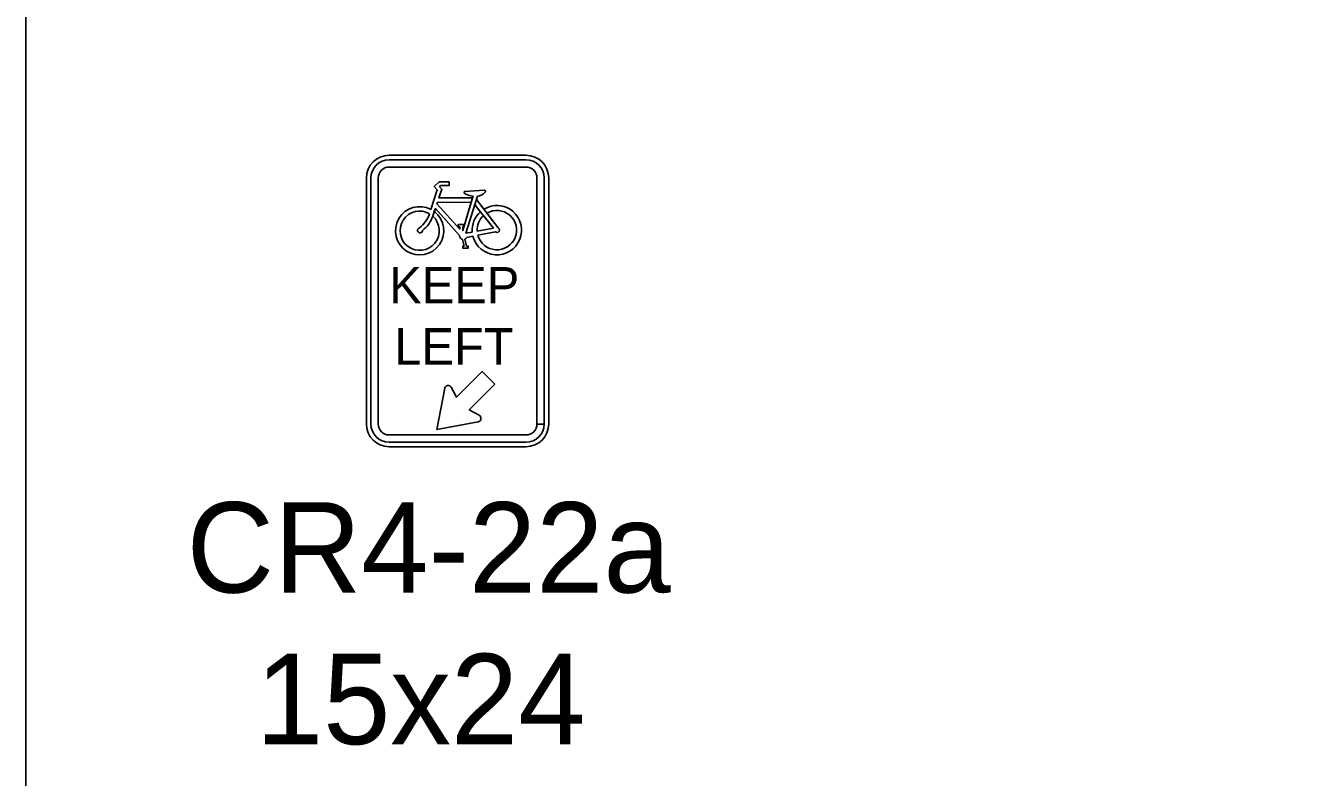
# Model space of a CAD drawing. Extents: x 1458 to 4498, y 17709 to 24109.
# Drawn here: x 1458.4 to 1670.2, y 20684 to 20807.7 of the extents above; entities that cross this region are included whole.
import ezdxf

# ---------------------------------------------------------------- set-up
doc = ezdxf.new("R2010")
doc.units = 0
doc.layers.add('P_TRAF_TCP_General', color=7, linetype='Continuous')

msp = doc.modelspace()

# ---------------------------------------------------------------- linework, layer by layer
at = {"layer": 'P_TRAF_TCP_General'}
for p, q in [((1518.22, 20786.39), (1540.72, 20786.39)), ((1518.22, 20785.64), (1540.72, 20785.64)), ((1540.72, 20784.44), (1518.22, 20784.44)), ((1514.47, 20742.14), (1514.47, 20782.64)), ((1515.22, 20742.14), (1515.22, 20782.64)), ((1516.42, 20782.64), (1516.42, 20742.14)), ((1542.52, 20742.14), (1542.52, 20782.64)), ((1543.72, 20782.64), (1543.72, 20742.14)), ((1544.47, 20782.64), (1544.47, 20742.14)), ((1542.52, 20742.14), (1543.72, 20742.14)), ((1518.22, 20740.34), (1540.72, 20740.34)), ((1540.72, 20739.14), (1518.22, 20739.14)), ((1540.72, 20738.39), (1518.22, 20738.39))]:
    msp.add_line(p, q, dxfattribs=at)
for points in [[(4498.44, 21909.14), (1458.44, 21909.14), (1458.44, 19909.14), (4498.44, 19909.14)], [(1526.07, 20778.38), (1529.84, 20774.23), (1529.84, 20774.6), (1529.57, 20774.6), (1529.57, 20774.96), (1530.45, 20774.96), (1530.45, 20774.6), (1530.31, 20774.6), (1530.31, 20773.97), (1531.72, 20778.67), (1526.15, 20778.63)]]:
    msp.add_lwpolyline(points, close=True, dxfattribs=at)
for points in [[(1525.07, 20777.47), (1526.12, 20780.71), (1525.63, 20781.22), (1526.43, 20781.99), (1528.1, 20781.99), (1528.1, 20781.42), (1526.68, 20781.42), (1526.47, 20781.19), (1526.88, 20780.78), (1526.4, 20779.35), (1531.93, 20779.37), (1532.02, 20779.68)], [(1525.07, 20777.47), (1526.12, 20780.71), (1525.63, 20781.22), (1526.43, 20781.99), (1528.1, 20781.99), (1528.1, 20781.42), (1526.68, 20781.42), (1526.47, 20781.19), (1526.88, 20780.78)], [(1525.07, 20777.47), (1526.12, 20780.71), (1525.63, 20781.22), (1526.43, 20781.99), (1528.1, 20781.99), (1528.1, 20781.42), (1526.68, 20781.42), (1526.47, 20781.19), (1526.88, 20780.78)], [(1526.88, 20780.78), (1526.4, 20779.35), (1531.93, 20779.37), (1531.72, 20778.67), (1526.15, 20778.63), (1526.07, 20778.38), (1529.84, 20774.23), (1529.84, 20774.6), (1529.57, 20774.6), (1529.57, 20774.96), (1530.45, 20774.96), (1530.45, 20774.6), (1530.31, 20774.6), (1530.31, 20773.97), (1532.02, 20779.68)], [(1526.88, 20780.78), (1526.4, 20779.35), (1531.93, 20779.37), (1531.72, 20778.67), (1526.15, 20778.63), (1526.07, 20778.38), (1529.84, 20774.23), (1529.84, 20774.6), (1529.57, 20774.6), (1529.57, 20774.96), (1530.45, 20774.96), (1530.45, 20774.6), (1530.31, 20774.6), (1530.31, 20773.97), (1532.02, 20779.68)], [(1530.67, 20780.43), (1533.84, 20780.64)], [(1530.67, 20780.43), (1533.84, 20780.64)], [(1530.67, 20780.43), (1533.84, 20780.64)], [(1532.73, 20779.66), (1530.85, 20773.55), (1531.88, 20773.74)], [(1532.73, 20779.66), (1530.85, 20773.55), (1531.88, 20773.74)], [(1532.73, 20779.66), (1532.56, 20779.09), (1533.78, 20777.51)], [(1529.81, 20773.18), (1525.81, 20777.61), (1525.39, 20776.37)], [(1529.81, 20773.18), (1525.81, 20777.61), (1525.39, 20776.37)], [(1529.81, 20773.18), (1525.81, 20777.61), (1525.64, 20777.11)], [(1530.85, 20773.55), (1532.3, 20778.25), (1533.21, 20777.09)], [(1532.69, 20773.89), (1535.36, 20774.37), (1532.3, 20778.24), (1532.56, 20779.08), (1536.17, 20774.44)], [(1532.69, 20773.89), (1535.36, 20774.37), (1532.3, 20778.24), (1532.56, 20779.08), (1536.17, 20774.44)], [(1534.29, 20776.86), (1533.78, 20777.51)], [(1534.29, 20776.86), (1533.78, 20777.51)], [(1525.39, 20776.37), (1525.64, 20777.11)], [(1525.39, 20776.37), (1525.64, 20777.11)], [(1532.69, 20773.89), (1535.36, 20774.37), (1533.73, 20776.44)], [(1533.21, 20777.08), (1533.73, 20776.44)], [(1533.21, 20777.08), (1533.73, 20776.44)], [(1534.29, 20776.85), (1536.17, 20774.44)], [(1531.88, 20773.74), (1530.85, 20773.55)], [(1535.73, 20773.76), (1532.8, 20773.21)], [(1535.73, 20773.76), (1532.8, 20773.21)], [(1535.73, 20773.76), (1532.8, 20773.21)], [(1530.66, 20772.56), (1530.94, 20771.43), (1531.23, 20771.43), (1531.23, 20771.1), (1530.35, 20771.1), (1530.35, 20771.43), (1530.55, 20771.43), (1530.27, 20772.52)], [(1530.66, 20772.56), (1530.94, 20771.43), (1531.23, 20771.43), (1531.23, 20771.1), (1530.35, 20771.1), (1530.35, 20771.43), (1530.55, 20771.43), (1530.27, 20772.52)], [(1530.35, 20771.43), (1530.55, 20771.43), (1530.27, 20772.52)], [(1530.66, 20772.56), (1530.94, 20771.43), (1531.23, 20771.43), (1531.23, 20771.1), (1530.35, 20771.1), (1530.35, 20771.43)], [(1531.99, 20773.06), (1530.97, 20772.87)], [(1531.99, 20773.06), (1530.97, 20772.87)], [(1531.99, 20773.06), (1530.97, 20772.87)], [(1535.61, 20748.68), (1533.51, 20750.78), (1529.29, 20746.56), (1528.42, 20748.19)], [(1535.61, 20748.68), (1533.51, 20750.78), (1529.29, 20746.56), (1528.42, 20748.19)], [(1535.61, 20748.68), (1533.51, 20750.78), (1529.29, 20746.56), (1528.42, 20748.19)], [(1527.35, 20748.03), (1526.08, 20741.25), (1532.86, 20742.52)], [(1527.35, 20748.03), (1526.08, 20741.25), (1532.86, 20742.52)], [(1527.35, 20748.03), (1526.08, 20741.25), (1532.86, 20742.52)], [(1533.02, 20743.59), (1531.39, 20744.46), (1535.61, 20748.68)], [(1533.02, 20743.59), (1531.39, 20744.46), (1535.61, 20748.68)], [(1533.02, 20743.59), (1531.39, 20744.46), (1535.61, 20748.68)]]:
    msp.add_lwpolyline(points, dxfattribs=at)
for centre, radius, start, end in [((1518.22, 20782.64), 3.75, 90, 180), ((1540.72, 20782.64), 3.75, 0, 90), ((1518.22, 20782.64), 3, 90, 180), ((1518.22, 20782.64), 1.8, 90, 180), ((1540.72, 20782.64), 3, 0, 90), ((1540.72, 20782.64), 1.8, 0, 90), ((1530.68, 20780.31), 0.124, 93.7117, 196.8473), ((1530.68, 20780.31), 0.124, 93.7117, 196.8473), ((1530.68, 20780.31), 0.124, 93.7117, 196.8473), ((1531, 20780.4), 0.454, 196.8473, 247.1714), ((1531, 20780.4), 0.454, 196.8473, 247.1714), ((1531, 20780.4), 0.454, 196.8473, 247.1714), ((1532.34, 20783.44), 3.78, 246.2052, 265.1291), ((1532.34, 20783.44), 3.78, 246.2052, 265.1291), ((1532.34, 20783.44), 3.78, 246.2052, 265.1291), ((1532.61, 20781.51), 1.85, 273.7836, 319.0624), ((1532.61, 20781.51), 1.85, 273.7836, 319.0624), ((1532.61, 20781.51), 1.85, 273.7836, 319.0624), ((1533.85, 20780.43), 0.207, 319.0624, 93.7117), ((1533.85, 20780.43), 0.207, 319.0624, 93.7117), ((1533.85, 20780.43), 0.207, 319.0624, 93.7117), ((1523.23, 20773.96), 3.97, 62.2493, 52.53), ((1523.23, 20773.96), 3.97, 62.2493, 52.4985), ((1523.23, 20773.96), 3.97, 62.2493, 52.4985), ((1535.93, 20774.06), 4.06, 194.2461, 121.8851), ((1535.93, 20774.06), 4.06, 194.2461, 121.8558), ((1535.93, 20774.06), 4.06, 194.2461, 121.8558), ((1523.23, 20773.96), 3.23, 59.9908, 48.0532), ((1523.23, 20773.96), 3.23, 59.9908, 48.0133), ((1523.23, 20773.96), 3.23, 59.9908, 48.0133), ((1520.19, 20778.29), 4.9, 308.2875, 341.8191), ((1520.19, 20778.29), 4.9, 308.2875, 341.8191), ((1520.19, 20778.29), 4.9, 308.2875, 341.8191), ((1520.66, 20777.96), 4.99, 307.7974, 341.3197), ((1520.66, 20777.96), 4.99, 307.7974, 341.3197), ((1520.66, 20777.96), 4.99, 307.7974, 341.3197), ((1535.93, 20774.06), 4.06, 131.8798, 184.5252), ((1535.93, 20774.06), 4.06, 131.909, 184.5252), ((1535.93, 20774.06), 4.06, 131.909, 184.5252), ((1535.93, 20774.06), 3.24, 132.7787, 183.036), ((1535.93, 20774.06), 3.24, 132.8154, 183.036), ((1535.93, 20774.06), 3.24, 132.8154, 183.036), ((1535.93, 20774.06), 3.24, 195.1748, 120.3535), ((1535.93, 20774.06), 3.24, 195.1748, 120.3165), ((1535.93, 20774.06), 3.24, 195.1748, 120.3165), ((1523.3, 20774.03), 0.422, 99.9437, 358.8663), ((1523.3, 20774.03), 0.422, 99.9437, 358.8663), ((1523.3, 20774.03), 0.422, 99.9437, 358.8663), ((1535.97, 20774.09), 0.407, 233.7627, 60.8531), ((1535.97, 20774.09), 0.407, 233.7627, 60.8531), ((1535.97, 20774.09), 0.407, 233.7627, 60.8531), ((1530.41, 20773.11), 0.605, 173.0491, 255.861), ((1530.41, 20773.11), 0.605, 173.0491, 255.861), ((1530.41, 20773.11), 0.605, 173.0491, 255.861), ((1530.41, 20773.11), 0.605, 294.6322, 336.7292), ((1530.41, 20773.11), 0.605, 294.6322, 336.7292), ((1530.41, 20773.11), 0.605, 294.6322, 336.7292), ((1527.91, 20747.92), 0.577, 27.9427, 169.3997), ((1527.91, 20747.92), 0.577, 27.9427, 169.3997), ((1527.91, 20747.92), 0.577, 27.9427, 169.3997), ((1532.75, 20743.08), 0.577, 280.6003, 62.0573), ((1532.75, 20743.08), 0.577, 280.6003, 62.0573), ((1532.75, 20743.08), 0.577, 280.6003, 62.0573), ((1518.22, 20742.14), 3.75, 180, 270), ((1518.22, 20742.14), 3, 180, 270), ((1518.22, 20742.14), 1.8, 180, 270), ((1540.72, 20742.14), 3.75, 270, 0), ((1540.72, 20742.14), 3, 270, 0), ((1540.72, 20742.14), 1.8, 270, 0)]:
    msp.add_arc(centre, radius, start, end, dxfattribs=at)

# ---------------------------------------------------------------- texts
for s, height, p in [('KEEP', 6, (1518.22, 20761.98)), ('LEFT', 6, (1519.06, 20751.92)), ('CR4-22a', 14.88, (1484.9, 20714.39)), ('15x24', 14.88, (1496.28, 20689.43))]:
    msp.add_text(s, height=height, dxfattribs=at).set_placement(p)

doc.saveas('drawing.dxf')
